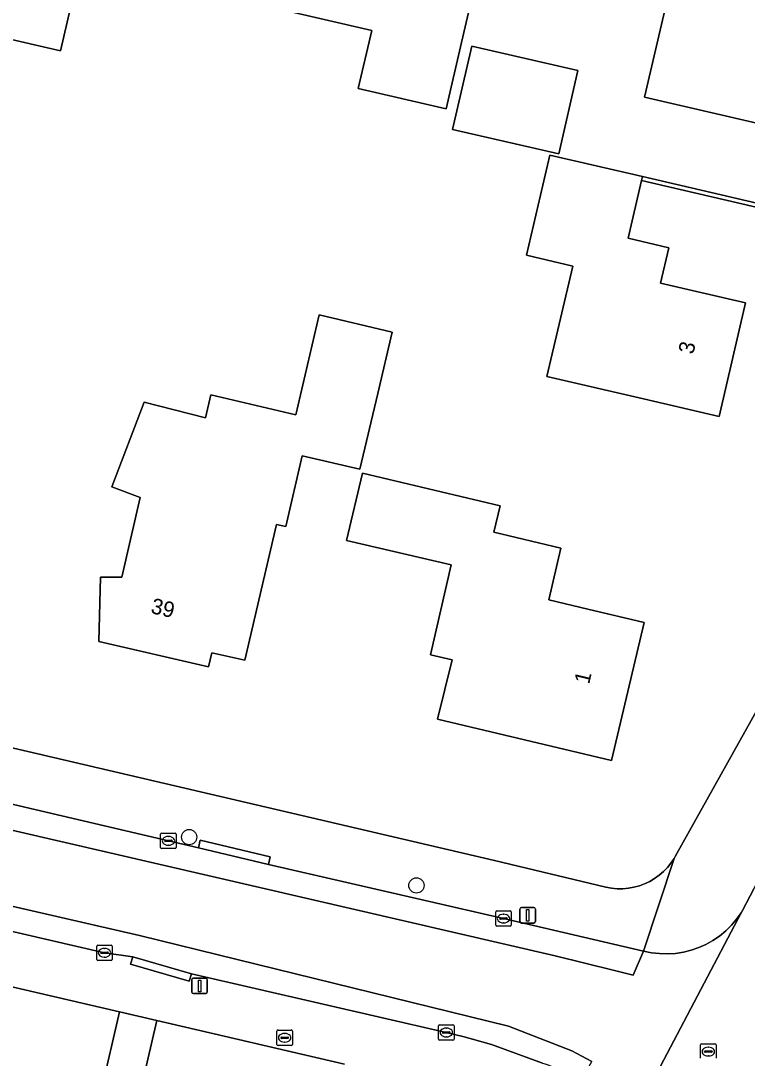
# Model space of a CAD drawing. Extents: x 162184 to 163154, y 385507 to 386516.
# Drawn here: x 162587.2 to 162633.8, y 385668.7 to 385735.4 of the extents above; entities that cross this region are included whole.
import ezdxf

# ---------------------------------------------------------------- set-up
doc = ezdxf.new("R2010")
doc.units = 0
for name, color, linetype in [('IMGEO_Boom', 7, 'Continuous'), ('IMGEO_Brandkraan', 7, 'Continuous'), ('IMGEO_Erf', 7, 'Continuous'), ('IMGEO_Grasland_overig', 7, 'Continuous'), ('IMGEO_Groenvoorziening', 7, 'Continuous'), ('IMGEO_Kolk', 7, 'Continuous'), ('IMGEO_Lichtmast', 7, 'Continuous'), ('IMGEO_Muur', 7, 'Continuous'), ('IMGEO_Pand', 7, 'Continuous'), ('IMGEO_Pand_nummerreeks', 7, 'Continuous'), ('IMGEO_Rijbaan_lokaal_gesloten', 7, 'Continuous'), ('IMGEO_Rioolput', 7, 'Continuous'), ('IMGEO_Voetpad_open', 7, 'Continuous')]:
    doc.layers.add(name, color=color, linetype=linetype)

msp = doc.modelspace()

# ---------------------------------------------------------------- linework, layer by layer
at = {"layer": 'IMGEO_Boom'}
for centre in [(162598.007, 385682.908), (162612.604, 385679.803)]:
    msp.add_circle(centre, 0.489, dxfattribs=at)
at = {"layer": 'IMGEO_Brandkraan'}
for p, q in [((162603.641, 385669.586), (162603.641, 385670.438)), ((162603.716, 385670.512), (162604.568, 385670.512)), ((162604.129, 385670.292), (162604.154, 385670.292)), ((162604.642, 385670.438), (162604.642, 385669.586)), ((162603.9, 385670.006), (162603.9, 385670.018)), ((162604.338, 385669.969), (162603.94, 385669.969)), ((162603.943, 385670.055), (162604.341, 385670.055)), ((162604.152, 385669.732), (162604.127, 385669.732)), ((162604.384, 385670.018), (162604.384, 385670.006)), ((162604.568, 385669.512), (162603.716, 385669.512))]:
    msp.add_line(p, q, dxfattribs=at)
for points in [[(162603.641, 385669.586), (162603.641, 385670.438)], [(162603.716, 385670.512), (162604.568, 385670.512)], [(162604.642, 385670.438), (162604.642, 385669.586)], [(162604.568, 385669.512), (162603.716, 385669.512)]]:
    msp.add_lwpolyline(points, dxfattribs=at)
for centre, radius, start, end in [((162603.718, 385670.436), 0.0765, 91.55205, 178.44795), ((162603.718, 385670.436), 0.0765, 91.55205, 178.44795), ((162604.566, 385670.436), 0.0765, 1.55205, 88.44795), ((162604.566, 385670.436), 0.0765, 1.55205, 88.44795), ((162603.94, 385670.015), 0.0403, 85.87752, 175.75265), ((162603.937, 385670.005), 0.0366, 178.93798, 274.71019), ((162604.341, 385670.012), 0.043, 264.86636, 352.45326), ((162604.345, 385670.017), 0.0386, 1.73085, 96.63898), ((162603.718, 385669.588), 0.0765, 181.55205, 268.44795), ((162603.718, 385669.588), 0.0765, 181.55205, 268.44795), ((162604.566, 385669.588), 0.0765, 271.55205, 358.44795), ((162604.566, 385669.588), 0.0765, 271.55205, 358.44795)]:
    msp.add_arc(centre, radius, start, end, dxfattribs=at)
for centre, major_axis, ratio, start_param, end_param in [((162604.128, 385670.012), (-0.387, 0.002), 0.722429, 4.712389, 7.853982), ((162604.153, 385670.012), (-0.39, 0.002), 0.717154, 1.570796, 4.712389)]:
    msp.add_ellipse(centre, major_axis=major_axis, ratio=ratio, start_param=start_param, end_param=end_param, dxfattribs=at)
at = {"layer": 'IMGEO_Erf'}
for points in [[(162629.644, 385740.745), (162632.266, 385740.137), (162632.374, 385740.602), (162633.146, 385740.423), (162632.765, 385738.781), (162638.563, 385737.436), (162638.767, 385738.317), (162642.56, 385737.437), (162640.803, 385729.86), (162639.369, 385730.193), (162638.812, 385727.79), (162627.26, 385730.469)], [(162616.16, 385733.748), (162622.975, 385732.178), (162621.738, 385726.813), (162614.924, 385728.384)], [(162621.173, 385726.735), (162627.116, 385725.352), (162630.245, 385724.624), (162635.114, 385723.491), (162635.056, 385723.242), (162627.058, 385725.103), (162626.193, 385721.389), (162628.81, 385720.78), (162628.284, 385718.517), (162633.746, 385717.246), (162632.045, 385709.938), (162627.176, 385711.071), (162620.985, 385712.511), (162622.637, 385719.608), (162619.675, 385720.298)], [(162595.122, 385710.864), (162599.064, 385709.847), (162599.41, 385711.33), (162604.861, 385710.05), (162606.367, 385716.462), (162611.044, 385715.364), (162610.12, 385711.422), (162608.979, 385706.553), (162605.257, 385707.413), (162604.206, 385702.863), (162603.612, 385703), (162601.594, 385694.27), (162599.469, 385694.761), (162599.26, 385693.856), (162592.198, 385695.488), (162592.315, 385699.607), (162593.684, 385699.614), (162594.868, 385704.738), (162593.053, 385705.429)], [(162609.147, 385706.307), (162617.98, 385704.201), (162617.575, 385702.502), (162621.887, 385701.474), (162621.097, 385698.162), (162623.617, 385697.561), (162627.233, 385696.699), (162625.122, 385687.836), (162613.96, 385690.495), (162614.903, 385694.306), (162613.51, 385694.628), (162614.844, 385700.406), (162608.111, 385701.961)]]:
    msp.add_lwpolyline(points, close=True, dxfattribs=at)
for points in [[(162616.627, 385738.848), (162615.505, 385733.976), (162614.523, 385729.713), (162608.871, 385731.015), (162609.732, 385734.747), (162602.498, 385736.416)], [(162478.146, 385714.062), (162478.381, 385713.959), (162478.624, 385713.877), (162478.764, 385713.841), (162500, 385708.882), (162617.624, 385681.414), (162624.775, 385679.694), (162625.131, 385679.628), (162625.491, 385679.594), (162625.852, 385679.592), (162626.213, 385679.622), (162626.569, 385679.685), (162626.918, 385679.779), (162627.258, 385679.904), (162627.585, 385680.059), (162627.897, 385680.242), (162628.191, 385680.452), (162628.465, 385680.688), (162628.717, 385680.948), (162628.945, 385681.229), (162629.147, 385681.529), (162629.224, 385681.661), (162660.237, 385737.235)], [(162590.664, 385737.422), (162589.745, 385733.438), (162585.751, 385734.36), (162586.187, 385736.249)]]:
    msp.add_lwpolyline(points, dxfattribs=at)
at = {"layer": 'IMGEO_Grasland_overig'}
msp.add_lwpolyline([(162607.987, 385668.312), (162595.943, 385671.116), (162594.761, 385666.037)], dxfattribs=at)
at = {"layer": 'IMGEO_Groenvoorziening'}
msp.add_lwpolyline([(162593.532, 385671.677), (162582.915, 385674.148), (162581.743, 385669.004), (162592.348, 385666.587)], close=True, dxfattribs=at)
at = {"layer": 'IMGEO_Kolk'}
for p, q in [((162596.176, 385682.243), (162596.176, 385683.095)), ((162596.251, 385683.169), (162597.103, 385683.169)), ((162596.664, 385682.949), (162596.689, 385682.949)), ((162597.177, 385683.095), (162597.177, 385682.243)), ((162596.435, 385682.663), (162596.435, 385682.675)), ((162596.873, 385682.626), (162596.475, 385682.626)), ((162596.478, 385682.712), (162596.876, 385682.712)), ((162596.687, 385682.389), (162596.662, 385682.389)), ((162596.919, 385682.675), (162596.919, 385682.663)), ((162597.103, 385682.169), (162596.251, 385682.169)), ((162617.693, 385677.249), (162617.693, 385678.101)), ((162617.768, 385678.175), (162618.62, 385678.175)), ((162617.952, 385677.669), (162617.952, 385677.681)), ((162618.39, 385677.632), (162617.992, 385677.632)), ((162617.995, 385677.718), (162618.393, 385677.718)), ((162618.181, 385677.955), (162618.206, 385677.955)), ((162618.436, 385677.681), (162618.436, 385677.669)), ((162618.694, 385678.101), (162618.694, 385677.249)), ((162618.62, 385677.175), (162617.768, 385677.175)), ((162618.204, 385677.395), (162618.179, 385677.395)), ((162592.069, 385675.048), (162592.069, 385675.9)), ((162592.144, 385675.974), (162592.996, 385675.974)), ((162592.557, 385675.754), (162592.582, 385675.754)), ((162593.07, 385675.9), (162593.07, 385675.048)), ((162592.996, 385674.974), (162592.144, 385674.974)), ((162592.328, 385675.468), (162592.328, 385675.48)), ((162592.766, 385675.431), (162592.368, 385675.431)), ((162592.371, 385675.517), (162592.769, 385675.517)), ((162592.58, 385675.194), (162592.555, 385675.194)), ((162592.812, 385675.48), (162592.812, 385675.468)), ((162614.02, 385669.927), (162614.02, 385670.779)), ((162614.095, 385670.853), (162614.947, 385670.853)), ((162614.279, 385670.347), (162614.279, 385670.359)), ((162614.717, 385670.31), (162614.319, 385670.31)), ((162614.322, 385670.396), (162614.72, 385670.396)), ((162614.508, 385670.633), (162614.533, 385670.633)), ((162614.763, 385670.359), (162614.763, 385670.347)), ((162615.021, 385670.779), (162615.021, 385669.927)), ((162614.947, 385669.853), (162614.095, 385669.853)), ((162614.531, 385670.073), (162614.506, 385670.073))]:
    msp.add_line(p, q, dxfattribs=at)
for points in [[(162596.176, 385682.243), (162596.176, 385683.095)], [(162596.251, 385683.169), (162597.103, 385683.169)], [(162597.177, 385683.095), (162597.177, 385682.243)], [(162597.103, 385682.169), (162596.251, 385682.169)], [(162617.693, 385677.249), (162617.693, 385678.101)], [(162617.768, 385678.175), (162618.62, 385678.175)], [(162618.694, 385678.101), (162618.694, 385677.249)], [(162618.62, 385677.175), (162617.768, 385677.175)], [(162592.069, 385675.048), (162592.069, 385675.9)], [(162592.144, 385675.974), (162592.996, 385675.974)], [(162593.07, 385675.9), (162593.07, 385675.048)], [(162592.996, 385674.974), (162592.144, 385674.974)], [(162614.02, 385669.927), (162614.02, 385670.779)], [(162614.095, 385670.853), (162614.947, 385670.853)], [(162615.021, 385670.779), (162615.021, 385669.927)], [(162614.947, 385669.853), (162614.095, 385669.853)]]:
    msp.add_lwpolyline(points, dxfattribs=at)
for centre, radius, start, end in [((162596.253, 385683.093), 0.0765, 91.55205, 178.44795), ((162596.253, 385683.093), 0.0765, 91.55205, 178.44795), ((162597.101, 385683.093), 0.0765, 1.55205, 88.44795), ((162597.101, 385683.093), 0.0765, 1.55205, 88.44795), ((162596.475, 385682.672), 0.0403, 85.87752, 175.75265), ((162596.472, 385682.662), 0.0366, 178.93798, 274.71019), ((162596.876, 385682.669), 0.043, 264.86636, 352.45326), ((162596.88, 385682.674), 0.0386, 1.73085, 96.63898), ((162596.253, 385682.245), 0.0765, 181.55205, 268.44795), ((162596.253, 385682.245), 0.0765, 181.55205, 268.44795), ((162597.101, 385682.245), 0.0765, 271.55205, 358.44795), ((162597.101, 385682.245), 0.0765, 271.55205, 358.44795), ((162617.77, 385678.099), 0.0765, 91.55205, 178.44795), ((162617.77, 385678.099), 0.0765, 91.55205, 178.44795), ((162617.992, 385677.678), 0.0403, 85.87752, 175.75265), ((162617.989, 385677.668), 0.0366, 178.93798, 274.71019), ((162618.393, 385677.675), 0.043, 264.86636, 352.45326), ((162618.397, 385677.68), 0.0386, 1.73085, 96.63898), ((162618.618, 385678.099), 0.0765, 1.55205, 88.44795), ((162618.618, 385678.099), 0.0765, 1.55205, 88.44795), ((162617.77, 385677.251), 0.0765, 181.55205, 268.44795), ((162617.77, 385677.251), 0.0765, 181.55205, 268.44795), ((162618.618, 385677.251), 0.0765, 271.55205, 358.44795), ((162618.618, 385677.251), 0.0765, 271.55205, 358.44795), ((162592.146, 385675.898), 0.0765, 91.55205, 178.44795), ((162592.146, 385675.898), 0.0765, 91.55205, 178.44795), ((162592.994, 385675.898), 0.0765, 1.55205, 88.44795), ((162592.994, 385675.898), 0.0765, 1.55205, 88.44795), ((162592.146, 385675.05), 0.0765, 181.55205, 268.44795), ((162592.146, 385675.05), 0.0765, 181.55205, 268.44795), ((162592.368, 385675.477), 0.0403, 85.87752, 175.75265), ((162592.365, 385675.467), 0.0366, 178.93798, 274.71019), ((162592.769, 385675.474), 0.043, 264.86636, 352.45326), ((162592.773, 385675.479), 0.0386, 1.73085, 96.63898), ((162592.994, 385675.05), 0.0765, 271.55205, 358.44795), ((162592.994, 385675.05), 0.0765, 271.55205, 358.44795), ((162614.097, 385670.777), 0.0765, 91.55205, 178.44795), ((162614.097, 385670.777), 0.0765, 91.55205, 178.44795), ((162614.319, 385670.356), 0.0403, 85.87752, 175.75265), ((162614.316, 385670.346), 0.0366, 178.93798, 274.71019), ((162614.72, 385670.353), 0.043, 264.86636, 352.45326), ((162614.724, 385670.358), 0.0386, 1.73085, 96.63898), ((162614.945, 385670.777), 0.0765, 1.55205, 88.44795), ((162614.945, 385670.777), 0.0765, 1.55205, 88.44795), ((162614.097, 385669.929), 0.0765, 181.55205, 268.44795), ((162614.097, 385669.929), 0.0765, 181.55205, 268.44795), ((162614.945, 385669.929), 0.0765, 271.55205, 358.44795), ((162614.945, 385669.929), 0.0765, 271.55205, 358.44795)]:
    msp.add_arc(centre, radius, start, end, dxfattribs=at)
for centre, major_axis, ratio, start_param, end_param in [((162596.663, 385682.669), (-0.387, 0.002), 0.722429, 4.712389, 7.853982), ((162596.688, 385682.669), (-0.39, 0.002), 0.717154, 1.570796, 4.712389), ((162618.18, 385677.675), (-0.387, 0.002), 0.722429, 4.712389, 7.853982), ((162618.205, 385677.675), (-0.39, 0.002), 0.717154, 1.570796, 4.712389), ((162592.556, 385675.474), (-0.387, 0.002), 0.722429, 4.712389, 7.853982), ((162592.581, 385675.474), (-0.39, 0.002), 0.717154, 1.570796, 4.712389), ((162614.507, 385670.353), (-0.387, 0.002), 0.722429, 4.712389, 7.853982), ((162614.532, 385670.353), (-0.39, 0.002), 0.717154, 1.570796, 4.712389)]:
    msp.add_ellipse(centre, major_axis=major_axis, ratio=ratio, start_param=start_param, end_param=end_param, dxfattribs=at)
at = {"layer": 'IMGEO_Lichtmast'}
for p, q in [((162619.253, 385677.488), (162619.253, 385678.288)), ((162619.253, 385678.288), (162619.253, 385677.488)), ((162619.353, 385678.388), (162620.143, 385678.388)), ((162620.143, 385678.388), (162619.353, 385678.388)), ((162620.243, 385678.288), (162620.243, 385677.488)), ((162620.243, 385677.488), (162620.243, 385678.288)), ((162620.143, 385677.388), (162619.353, 385677.388)), ((162619.353, 385677.388), (162620.143, 385677.388)), ((162598.18, 385672.95), (162598.18, 385673.75)), ((162598.18, 385673.75), (162598.18, 385672.95)), ((162598.28, 385673.85), (162599.07, 385673.85)), ((162599.07, 385673.85), (162598.28, 385673.85)), ((162599.17, 385673.75), (162599.17, 385672.95)), ((162599.17, 385672.95), (162599.17, 385673.75)), ((162599.07, 385672.85), (162598.28, 385672.85)), ((162598.28, 385672.85), (162599.07, 385672.85))]:
    msp.add_line(p, q, dxfattribs=at)
for points in [[(162619.673, 385678.263), (162619.823, 385678.263), (162619.823, 385677.513), (162619.673, 385677.513), (162619.673, 385678.263)], [(162598.6, 385673.725), (162598.75, 385673.725), (162598.75, 385672.975), (162598.6, 385672.975), (162598.6, 385673.725)]]:
    msp.add_lwpolyline(points, dxfattribs=at)
for centre, start, end in [((162619.353, 385678.288), 90, 180), ((162619.353, 385678.288), 90, 180), ((162620.143, 385678.288), 0, 90), ((162620.143, 385678.288), 360, 90), ((162619.353, 385677.488), 180, 270), ((162619.353, 385677.488), 180, 270), ((162620.143, 385677.488), 270, 0), ((162620.143, 385677.488), 270, 0), ((162598.28, 385673.75), 90, 180), ((162598.28, 385673.75), 90, 180), ((162599.07, 385673.75), 0, 90), ((162599.07, 385673.75), 360, 90), ((162598.28, 385672.95), 180, 270), ((162598.28, 385672.95), 180, 270), ((162599.07, 385672.95), 270, 0), ((162599.07, 385672.95), 270, 0)]:
    msp.add_arc(centre, 0.1, start, end, dxfattribs=at)
at = {"layer": 'IMGEO_Muur'}
msp.add_lwpolyline([(162630.245, 385724.624), (162627.116, 385725.352), (162627.058, 385725.103), (162635.056, 385723.242), (162635.114, 385723.491)], close=True, dxfattribs=at)
at = {"layer": 'IMGEO_Pand'}
for points in [[(162588.092, 385742.628), (162589.015, 385746.631), (162589.775, 385749.924), (162589.445, 385750), (162582.209, 385751.669), (162581.807, 385750), (162579.72, 385741.324), (162579.71, 385741.282), (162580.073, 385741.198), (162583.835, 385740.33), (162583.06, 385736.97), (162586.187, 385736.249), (162585.751, 385734.36), (162589.745, 385733.438), (162590.664, 385737.422), (162590.886, 385737.371), (162592.812, 385745.755), (162592.577, 385745.809), (162591.654, 385741.806)], [(162602.498, 385736.416), (162609.732, 385734.747), (162608.871, 385731.015), (162614.523, 385729.713), (162615.505, 385733.976), (162616.627, 385738.848), (162612.689, 385739.755), (162613.028, 385741.226), (162611.39, 385741.603), (162612.127, 385744.799), (162604.82, 385746.485)], [(162638.812, 385727.79), (162639.369, 385730.193), (162640.803, 385729.86), (162642.56, 385737.437), (162638.767, 385738.317), (162638.563, 385737.436), (162632.765, 385738.781), (162633.146, 385740.423), (162632.374, 385740.602), (162632.266, 385740.137), (162629.644, 385740.745), (162627.26, 385730.469)], [(162614.924, 385728.384), (162621.738, 385726.813), (162622.975, 385732.178), (162616.16, 385733.748)], [(162628.81, 385720.78), (162626.193, 385721.389), (162627.058, 385725.103), (162627.116, 385725.352), (162621.173, 385726.735), (162619.675, 385720.298), (162622.637, 385719.608), (162620.985, 385712.511), (162627.176, 385711.071), (162632.045, 385709.938), (162633.746, 385717.246), (162628.284, 385718.517)], [(162605.257, 385707.413), (162608.979, 385706.553), (162610.12, 385711.422), (162611.044, 385715.364), (162606.367, 385716.462), (162604.861, 385710.05), (162599.41, 385711.33), (162599.064, 385709.847), (162595.122, 385710.864), (162593.053, 385705.429), (162594.868, 385704.738), (162593.684, 385699.614), (162592.315, 385699.607), (162592.198, 385695.488), (162599.26, 385693.856), (162599.469, 385694.761), (162601.594, 385694.27), (162603.612, 385703), (162604.206, 385702.863)], [(162623.617, 385697.561), (162621.097, 385698.162), (162621.887, 385701.474), (162617.575, 385702.502), (162617.98, 385704.201), (162609.147, 385706.307), (162608.111, 385701.961), (162614.844, 385700.406), (162613.51, 385694.628), (162614.903, 385694.306), (162613.96, 385690.495), (162625.122, 385687.836), (162627.233, 385696.699)]]:
    msp.add_lwpolyline(points, close=True, dxfattribs=at)
at = {"layer": 'IMGEO_Rijbaan_lokaal_gesloten'}
for points in [[(162635.245, 385668.306), (162636.519, 385670.855), (162638.267, 385674.113), (162639.551, 385676.532), (162639.639, 385676.697), (162640.899, 385679.008), (162650.908, 385696.998), (162660.533, 385714.063), (162669.626, 385730.286), (162670.453, 385731.763), (162665.225, 385734.704), (162634.605, 385680.278), (162634.528, 385680.074), (162633.547, 385678.184), (162633.464, 385678.05), (162624.375, 385660.767)], [(162564.579, 385688.443), (162621.523, 385675.27), (162625.332, 385674.33), (162626.529, 385674.034), (162627.196, 385675.586), (162618.19, 385677.674), (162603.102, 385681.153), (162598.599, 385682.225), (162596.673, 385682.668), (162581.228, 385686.28)], [(162624.375, 385660.767), (162633.464, 385678.05), (162633.168, 385677.631), (162632.835, 385677.239), (162632.469, 385676.879), (162632.071, 385676.553), (162631.647, 385676.263), (162631.198, 385676.013), (162630.729, 385675.804), (162630.243, 385675.637), (162629.744, 385675.515), (162629.236, 385675.438), (162628.723, 385675.406), (162628.209, 385675.42), (162627.699, 385675.48), (162627.196, 385675.586), (162626.529, 385674.034), (162625.332, 385674.33), (162621.523, 385675.27), (162564.579, 385688.443)], [(162582.293, 385677.847), (162592.566, 385675.475), (162594.389, 385675.222), (162598.157, 385674.119), (162614.518, 385670.354), (162615.678, 385670.071), (162617.428, 385669.572), (162620.71, 385668.39), (162620.941, 385668.314), (162621.418, 385668.122), (162621.876, 385667.887), (162622.311, 385667.613), (162622.72, 385667.301), (162623.043, 385667.006), (162623.857, 385668.491), (162622.59, 385669.165), (162618.525, 385670.768), (162594.827, 385676.576), (162561.442, 385684.248)], [(162561.442, 385684.248), (162594.827, 385676.576), (162618.525, 385670.768), (162622.59, 385669.165), (162623.857, 385668.491)]]:
    msp.add_lwpolyline(points, dxfattribs=at)
at = {"layer": 'IMGEO_Rioolput'}
for p, q in [((162630.921, 385669.623), (162631.773, 385669.623)), ((162630.846, 385668.697), (162630.846, 385669.549)), ((162631.105, 385669.117), (162631.105, 385669.129)), ((162631.543, 385669.08), (162631.145, 385669.08)), ((162631.148, 385669.166), (162631.546, 385669.166)), ((162631.334, 385669.403), (162631.359, 385669.403)), ((162631.589, 385669.129), (162631.589, 385669.117)), ((162631.847, 385669.549), (162631.847, 385668.697)), ((162631.357, 385668.843), (162631.332, 385668.843))]:
    msp.add_line(p, q, dxfattribs=at)
for points in [[(162630.921, 385669.623), (162631.773, 385669.623)], [(162630.846, 385668.697), (162630.846, 385669.549)], [(162631.847, 385669.549), (162631.847, 385668.697)]]:
    msp.add_lwpolyline(points, dxfattribs=at)
for centre, radius, start, end in [((162630.923, 385669.547), 0.0765, 91.55205, 178.44795), ((162630.923, 385669.547), 0.0765, 91.55205, 178.44795), ((162631.771, 385669.547), 0.0765, 1.55205, 88.44795), ((162631.771, 385669.547), 0.0765, 1.55205, 88.44795), ((162631.145, 385669.126), 0.0403, 85.87752, 175.75265), ((162631.142, 385669.116), 0.0366, 178.93798, 274.71019), ((162631.546, 385669.123), 0.043, 264.86636, 352.45326), ((162631.55, 385669.128), 0.0386, 1.73085, 96.63898)]:
    msp.add_arc(centre, radius, start, end, dxfattribs=at)
for centre, major_axis, ratio, start_param, end_param in [((162631.333, 385669.123), (-0.387, 0.002), 0.722429, 4.712389, 7.853982), ((162631.358, 385669.123), (-0.39, 0.002), 0.717154, 1.570796, 4.712389)]:
    msp.add_ellipse(centre, major_axis=major_axis, ratio=ratio, start_param=start_param, end_param=end_param, dxfattribs=at)
at = {"layer": 'IMGEO_Voetpad_open'}
for points in [[(162663.67, 385743.202), (162660.325, 385737.36), (162660.237, 385737.235), (162629.224, 385681.661), (162629.147, 385681.529), (162627.196, 385675.586), (162627.699, 385675.48), (162628.209, 385675.42), (162628.723, 385675.406), (162629.236, 385675.438), (162629.744, 385675.515), (162630.243, 385675.637), (162630.729, 385675.804), (162631.198, 385676.013), (162631.647, 385676.263), (162632.071, 385676.553), (162632.469, 385676.879), (162632.835, 385677.239), (162633.168, 385677.631), (162633.464, 385678.05), (162633.547, 385678.184), (162634.528, 385680.074), (162634.605, 385680.278)], [(162581.228, 385686.28), (162596.673, 385682.668), (162598.599, 385682.225), (162598.714, 385682.711), (162603.217, 385681.639), (162603.102, 385681.153), (162618.19, 385677.674), (162627.196, 385675.586), (162629.147, 385681.529), (162628.945, 385681.229), (162628.717, 385680.948), (162628.465, 385680.688), (162628.191, 385680.452), (162627.897, 385680.242), (162627.585, 385680.059), (162627.258, 385679.904), (162626.918, 385679.779), (162626.569, 385679.685), (162626.213, 385679.622), (162625.852, 385679.592), (162625.491, 385679.594), (162625.131, 385679.628), (162624.775, 385679.694), (162617.624, 385681.414), (162500, 385708.882)], [(162620.71, 385668.39), (162617.428, 385669.572), (162615.678, 385670.071), (162614.518, 385670.354), (162598.157, 385674.119), (162598.017, 385673.64), (162594.249, 385674.743), (162594.389, 385675.222), (162592.566, 385675.475), (162582.293, 385677.847)], [(162582.915, 385674.148), (162593.532, 385671.677), (162595.943, 385671.116), (162607.987, 385668.312)]]:
    msp.add_lwpolyline(points, dxfattribs=at)
for points in [[(162598.599, 385682.225), (162603.102, 385681.153), (162603.217, 385681.639), (162598.714, 385682.711)], [(162598.157, 385674.119), (162594.389, 385675.222), (162594.249, 385674.743), (162598.017, 385673.64)], [(162595.943, 385671.116), (162593.532, 385671.677), (162592.348, 385666.587), (162594.761, 385666.037)]]:
    msp.add_lwpolyline(points, close=True, dxfattribs=at)

# ---------------------------------------------------------------- texts
at = {"layer": 'IMGEO_Pand_nummerreeks'}
for s, rotation, p in [('3', 76.89667, (162630.378, 385713.895)), ('39', 346.98813, (162595.491, 385697.314)), ('1', 76.60284, (162623.689, 385692.694))]:
    msp.add_text(s, height=1, rotation=rotation, dxfattribs=at).set_placement(p)

doc.saveas('drawing.dxf')
